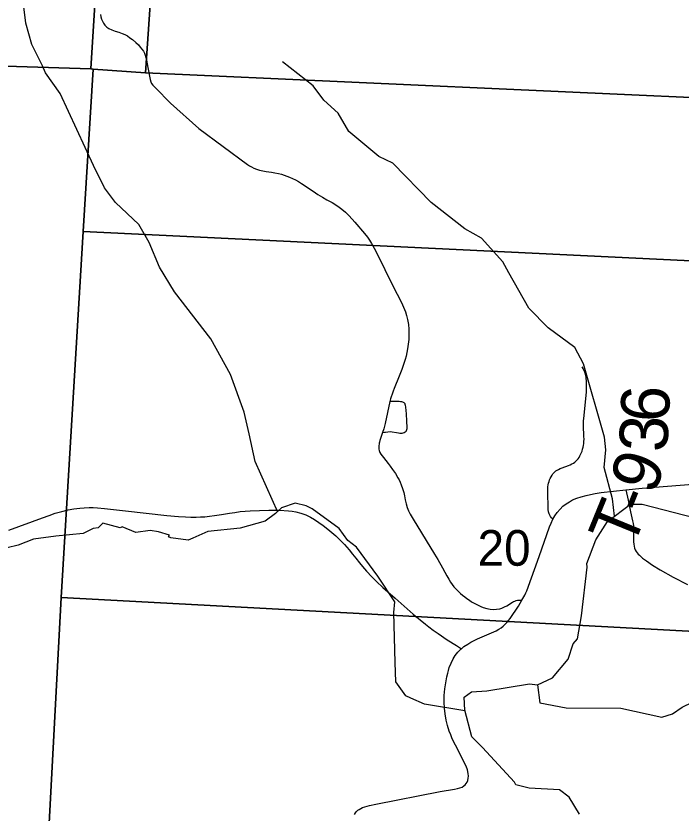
# Model space of a CAD drawing. Extents: x -2.1 to 31.9, y 6.3 to 28.3.
# Drawn here: x 1.171 to 1.952, y 21.042 to 21.978 of the extents above; entities that cross this region are included whole.
import ezdxf

# ---------------------------------------------------------------- set-up
doc = ezdxf.new("R2010")
doc.units = 0
for name, color, linetype in [('GM_X_County_Road', 7, 'Continuous'), ('GM_X_Minor_River', 7, 'Continuous'), ('GM_X_Section', 7, 'Continuous'), ('GM_X_Section_Text', 7, 'Continuous'), ('GM_X_State_Route', 7, 'Continuous'), ('GM_X_Township_Road', 7, 'Continuous'), ('GM_X_Township_Road_Text', 7, 'Continuous')]:
    doc.layers.add(name, color=color, linetype=linetype)

msp = doc.modelspace()

# ---------------------------------------------------------------- linework, layer by layer
at = {"layer": 'GM_X_County_Road'}
for points in [[(1.27034, 21.9797), (1.27105, 21.97669), (1.27184, 21.97421), (1.27282, 21.97174), (1.27399, 21.96952), (1.27563, 21.9671), (1.27778, 21.96488), (1.28039, 21.96305), (1.28387, 21.96149), (1.2877, 21.9601), (1.29221, 21.95868), (1.29579, 21.95744), (1.29912, 21.95607), (1.30215, 21.95434), (1.30508, 21.95238), (1.30795, 21.95009), (1.31196, 21.94681), (1.315, 21.94394), (1.31727, 21.94141), (1.31909, 21.93898), (1.32083, 21.93645), (1.32214, 21.93402), (1.32309, 21.93167), (1.32388, 21.92923), (1.32449, 21.9268), (1.32509, 21.92375), (1.32786, 21.90712), (1.32864, 21.90334), (1.32943, 21.90073), (1.33047, 21.89857), (1.33191, 21.89648), (1.33508, 21.89339), (1.35288, 21.87551), (1.38613, 21.84593), (1.44319, 21.80357), (1.44541, 21.80206), (1.44769, 21.8007), (1.4505, 21.79932), (1.45383, 21.79802), (1.45735, 21.79691), (1.46094, 21.79613), (1.46505, 21.79545), (1.46804, 21.79501), (1.47138, 21.79453), (1.47516, 21.7939), (1.47935, 21.79297), (1.483, 21.79199), (1.4862, 21.79101), (1.48934, 21.78984), (1.49244, 21.78862), (1.49606, 21.78703), (1.49953, 21.78539), (1.5031, 21.78344), (1.50663, 21.78137), (1.52014, 21.77205), (1.52582, 21.76835), (1.53104, 21.76522), (1.53644, 21.76212), (1.54252, 21.75879), (1.54934, 21.75455), (1.55383, 21.75129), (1.55804, 21.74768), (1.56243, 21.74334), (1.56912, 21.73604), (1.58046, 21.72269), (1.58385, 21.71834), (1.58637, 21.71477), (1.58881, 21.71069), (1.59177, 21.70529), (1.59491, 21.69963), (1.6137, 21.66102), (1.62382, 21.64163), (1.6263, 21.63615), (1.62845, 21.6308), (1.62988, 21.6263), (1.631, 21.62153), (1.63204, 21.61572), (1.63249, 21.61037), (1.63269, 21.60375), (1.63253, 21.59821), (1.63195, 21.59269), (1.63111, 21.58735), (1.63026, 21.58298), (1.62927, 21.57867), (1.62817, 21.57462), (1.62706, 21.57104), (1.62427, 21.56286), (1.62124, 21.55517), (1.61534, 21.54057), (1.61409, 21.53744), (1.61286, 21.53391), (1.61188, 21.53104), (1.61109, 21.52836), (1.61028, 21.52528)], [(1.61028, 21.52528), (1.60758, 21.51265), (1.60474, 21.49939), (1.60409, 21.49633), (1.60317, 21.49313), (1.60181, 21.48908), (1.5989, 21.48094), (1.59845, 21.47942), (1.59804, 21.47783), (1.59773, 21.47653), (1.59752, 21.47538), (1.59738, 21.47392), (1.59732, 21.47251), (1.59735, 21.471), (1.59746, 21.46949), (1.59771, 21.468), (1.59807, 21.46674), (1.59864, 21.46542), (1.59975, 21.46367), (1.60272, 21.45978), (1.60832, 21.4526), (1.61061, 21.44966), (1.6135, 21.44562), (1.61697, 21.44077), (1.61981, 21.43597), (1.62117, 21.43344), (1.62245, 21.43058), (1.62369, 21.42743), (1.625, 21.42343), (1.62648, 21.41873), (1.62743, 21.41455), (1.62839, 21.40986), (1.62935, 21.40533), (1.63058, 21.40102), (1.63219, 21.39715), (1.6343, 21.39319), (1.63777, 21.38722), (1.66287, 21.34609), (1.66669, 21.33983), (1.67199, 21.33031), (1.67468, 21.32523), (1.67713, 21.32081), (1.67946, 21.31686), (1.68159, 21.31341), (1.68349, 21.31067), (1.68549, 21.30803), (1.68741, 21.30578), (1.68924, 21.30379), (1.69123, 21.30186), (1.69332, 21.2999), (1.69569, 21.29795), (1.69819, 21.29596), (1.70078, 21.29413), (1.70383, 21.29203), (1.70631, 21.29046), (1.70917, 21.28879), (1.71472, 21.28595), (1.71712, 21.28488), (1.71991, 21.28375), (1.72413, 21.28247), (1.72785, 21.28176), (1.73164, 21.28144), (1.73546, 21.28157), (1.73922, 21.28224), (1.74164, 21.283), (1.74483, 21.28434), (1.74752, 21.28576), (1.75421, 21.28969), (1.75554, 21.29047), (1.75701, 21.29116), (1.75857, 21.29169), (1.76014, 21.29203), (1.762, 21.29218), (1.76539, 21.29221)], [(1.88742, 21.42157), (1.89001, 21.40957), (1.893, 21.39573), (1.89528, 21.38515), (1.89581, 21.38217), (1.8962, 21.3796), (1.8964, 21.37656), (1.89647, 21.37346), (1.89647, 21.36064), (1.89657, 21.35808), (1.89693, 21.35555), (1.89746, 21.35317), (1.89825, 21.35124), (1.8993, 21.3495), (1.90048, 21.34797), (1.90192, 21.34633), (1.9033, 21.34493), (1.90499, 21.34336), (1.90709, 21.34163), (1.91157, 21.33827), (1.91875, 21.3334), (1.92773, 21.32782), (1.9428, 21.31928), (1.95972, 21.31045)], [(1.16269, 21.37436), (1.20229, 21.38882), (1.21038, 21.39177), (1.21737, 21.39414), (1.22506, 21.39641), (1.23236, 21.39828), (1.23915, 21.39947), (1.24615, 21.40026), (1.25147, 21.40065), (1.25729, 21.40085), (1.26192, 21.40085), (1.26715, 21.40055), (1.27522, 21.39986), (1.3, 21.39688), (1.3485, 21.39175), (1.36216, 21.39044), (1.37018, 21.38992), (1.37648, 21.38979), (1.38293, 21.38979), (1.38778, 21.38992), (1.39291, 21.39018), (1.3983, 21.3907), (1.40446, 21.39154), (1.41249, 21.39267), (1.42194, 21.3943), (1.42812, 21.3953), (1.43444, 21.39609), (1.44626, 21.39688), (1.45711, 21.39745), (1.46828, 21.39771), (1.48067, 21.39771), (1.49115, 21.39719), (1.49548, 21.39669), (1.49992, 21.39601), (1.50574, 21.3945), (1.51156, 21.3922), (1.51697, 21.38957), (1.5218, 21.38681), (1.52703, 21.38346), (1.53186, 21.38001), (1.53737, 21.37567), (1.54229, 21.37162), (1.54674, 21.36769), (1.55147, 21.36306), (1.55689, 21.35744), (1.56229, 21.35138), (1.56643, 21.34636), (1.57018, 21.34163), (1.57461, 21.33601), (1.57825, 21.33158), (1.58289, 21.32616), (1.58913, 21.31959), (1.59442, 21.31403), (1.6022, 21.30694), (1.61659, 21.29452), (1.63768, 21.27589), (1.65207, 21.26387), (1.65601, 21.26081), (1.66104, 21.25707), (1.66715, 21.25293), (1.67752, 21.24568), (1.68841, 21.23889), (1.69422, 21.23526)]]:
    msp.add_lwpolyline(points, dxfattribs=at)
at = {"layer": 'GM_X_Minor_River'}
for points in [[(1.47874, 21.39561), (1.45219, 21.45492), (1.44524, 21.48741), (1.43921, 21.51304), (1.42316, 21.55721), (1.39986, 21.59896), (1.35731, 21.65422), (1.33966, 21.68287), (1.3277, 21.71211), (1.31548, 21.733), (1.28792, 21.75893), (1.27521, 21.77604), (1.2624, 21.80227), (1.22302, 21.88704), (1.20598, 21.91113), (1.20245, 21.91921), (1.18998, 21.94429), (1.18281, 21.96957), (1.17979, 21.99473), (1.17551, 22.00322)], [(1.87414, 21.39089), (1.8717, 21.41107), (1.86185, 21.44783), (1.864, 21.46865), (1.86218, 21.48351), (1.83758, 21.56972), (1.82757, 21.58864), (1.79614, 21.61166), (1.77341, 21.63478), (1.75011, 21.67652), (1.74294, 21.68928), (1.7177, 21.71703), (1.69837, 21.72789), (1.65887, 21.75876), (1.61378, 21.80499), (1.59739, 21.8131), (1.56679, 21.83836), (1.562, 21.84231), (1.54941, 21.86359), (1.53287, 21.87893), (1.52016, 21.89603), (1.48435, 21.92412)], [(1.69839, 21.16231), (1.65093, 21.17017), (1.63505, 21.17735), (1.629, 21.17999), (1.61726, 21.19631), (1.61649, 21.21911), (1.61492, 21.27763), (1.61604, 21.29017), (1.59598, 21.32053), (1.571, 21.35429), (1.56079, 21.36224), (1.55057, 21.37627), (1.51917, 21.39937), (1.51199, 21.40278), (1.49913, 21.40616), (1.48288, 21.40042), (1.47608, 21.39394), (1.464, 21.38479), (1.43452, 21.37673), (1.39672, 21.37283), (1.37896, 21.36481), (1.37329, 21.36251), (1.35325, 21.3655), (1.35023, 21.36664), (1.35136, 21.36854), (1.33851, 21.37231), (1.32868, 21.37418), (1.31205, 21.37148), (1.29579, 21.37828), (1.29352, 21.37714), (1.2731, 21.38278), (1.26781, 21.37707), (1.26177, 21.37629), (1.25005, 21.37057), (1.21792, 21.36744), (1.19184, 21.36396), (1.17371, 21.35669), (1.16086, 21.35362)], [(1.83287, 21.04105), (1.82076, 21.06116), (1.80941, 21.06949), (1.77387, 21.07168), (1.75837, 21.07544), (1.75648, 21.07847), (1.71902, 21.11942), (1.70653, 21.13193), (1.69819, 21.16307), (1.69742, 21.17827), (1.70611, 21.18475), (1.72425, 21.18594), (1.77414, 21.19406), (1.78359, 21.19294), (1.80135, 21.20097), (1.81947, 21.22306), (1.8255, 21.24094), (1.83041, 21.24703), (1.8353, 21.27365), (1.84205, 21.33106), (1.84167, 21.33523), (1.85223, 21.36301), (1.86582, 21.38471), (1.89264, 21.40492), (1.90663, 21.40496), (1.96863, 21.38878)], [(1.78359, 21.19294), (1.78641, 21.1718), (1.81714, 21.16579), (1.88162, 21.16556), (1.92943, 21.15503), (1.94231, 21.15886), (1.9533, 21.16648), (1.96542, 21.17259), (1.99994, 21.17), (2.02916, 21.16247), (2.05535, 21.15113), (2.0903, 21.12955), (2.11497, 21.12314), (2.14916, 21.0989), (2.16093, 21.09095), (2.18483, 21.0891), (2.24512, 21.09531), (2.32482, 21.07345), (2.34834, 21.0697), (2.35974, 21.06212), (2.3643, 21.05871)]]:
    msp.add_lwpolyline(points, dxfattribs=at)
at = {"layer": 'GM_X_Section'}
for points in [[(1.31019, 22.73073), (1.25907, 21.91577), (0.77277, 21.931), (0.82184, 22.74075)], [(1.37956, 22.72918), (1.3414, 22.17396), (1.32333, 21.91114), (1.26179, 21.91558), (1.25907, 21.91577), (1.31019, 22.73073)], [(1.3414, 22.17396), (2.12451, 22.13845), (2.30887, 22.13009), (2.29227, 21.86725), (1.32333, 21.91114)], [(0.77277, 21.931), (1.25907, 21.91577), (1.26179, 21.91558), (1.25012, 21.72495), (1.22439, 21.29531), (1.2015, 20.86872), (0.16057, 20.92297), (0.22471, 21.95065)], [(1.32333, 21.91114), (2.29227, 21.86725), (2.28013, 21.67512), (1.25012, 21.72495), (1.26179, 21.91558)], [(1.25012, 21.72495), (2.28013, 21.67512), (2.25264, 21.24002), (1.22439, 21.29531)], [(2.25264, 21.24002), (2.2269, 20.81748), (1.2015, 20.86872), (1.22439, 21.29531)]]:
    msp.add_lwpolyline(points, close=True, dxfattribs=at)
at = {"layer": 'GM_X_State_Route'}
for points in [[(1.70182, 21.24071), (1.70549, 21.24289), (1.70939, 21.2449), (1.7132, 21.24666), (1.73507, 21.25641), (1.73828, 21.25817), (1.74096, 21.25993), (1.74318, 21.26169), (1.74545, 21.26373), (1.74755, 21.2659), (1.75145, 21.27073), (1.76138, 21.28505), (1.76539, 21.29221), (1.7686, 21.2981), (1.76991, 21.30078), (1.77099, 21.30335), (1.78555, 21.34336), (1.7979, 21.37818), (1.79959, 21.38247), (1.80173, 21.38721), (1.80395, 21.39105), (1.80671, 21.3951), (1.81015, 21.39916), (1.81352, 21.40253), (1.81735, 21.40544), (1.82103, 21.40781), (1.82486, 21.40988), (1.82968, 21.41195), (1.83481, 21.41363), (1.84071, 21.41524), (1.84584, 21.41639), (1.85128, 21.41731), (1.85853, 21.41839), (1.88742, 21.42157), (1.90644, 21.42366), (1.98099, 21.42947)], [(1.56857, 21.04069), (1.57001, 21.04282), (1.57127, 21.04436), (1.57254, 21.04558), (1.57403, 21.04673), (1.57603, 21.0479), (1.57833, 21.04893), (1.58091, 21.04985), (1.58349, 21.0506), (1.58644, 21.05127), (1.59373, 21.05274), (1.66923, 21.0677), (1.68613, 21.07038), (1.6896, 21.071), (1.69258, 21.07182), (1.69497, 21.07286), (1.6972, 21.07426), (1.69874, 21.07555), (1.70001, 21.07709), (1.70102, 21.0788), (1.70178, 21.08063), (1.70238, 21.08316), (1.70258, 21.08573), (1.70239, 21.08893), (1.70145, 21.09329), (1.69984, 21.09737), (1.68721, 21.12202), (1.68512, 21.12649), (1.68315, 21.13075), (1.68167, 21.13437), (1.68001, 21.13865), (1.67802, 21.145), (1.67649, 21.15151), (1.67511, 21.1587), (1.67434, 21.16559), (1.6739, 21.17245), (1.67394, 21.17649), (1.67406, 21.18027), (1.67432, 21.18414), (1.67473, 21.18811), (1.67547, 21.19303), (1.67626, 21.19768), (1.67715, 21.20206), (1.67817, 21.20641), (1.67906, 21.2098), (1.68008, 21.21307), (1.68223, 21.21844), (1.68476, 21.22356), (1.68698, 21.22709), (1.69012, 21.23122), (1.69349, 21.23467), (1.69422, 21.23526), (1.69731, 21.23773), (1.70182, 21.24071)]]:
    msp.add_lwpolyline(points, dxfattribs=at)
at = {"layer": 'GM_X_Township_Road'}
for points in [[(1.80173, 21.38721), (1.80015, 21.38882), (1.79906, 21.39026), (1.79809, 21.3918), (1.79722, 21.3937), (1.79662, 21.39599), (1.7963, 21.39858), (1.79613, 21.40145), (1.79573, 21.41782), (1.7957, 21.42059), (1.79574, 21.42293), (1.79586, 21.42515), (1.79612, 21.42745), (1.79665, 21.42968), (1.79716, 21.43158), (1.7979, 21.43347), (1.7986, 21.43499), (1.79954, 21.43683), (1.80078, 21.43894), (1.80177, 21.44041), (1.80281, 21.44161), (1.80402, 21.44282), (1.80528, 21.44383), (1.80674, 21.44482), (1.80838, 21.44576), (1.81037, 21.44672), (1.81239, 21.44754), (1.82009, 21.45044), (1.82211, 21.4512), (1.82406, 21.45214), (1.8257, 21.45309), (1.82738, 21.4543), (1.82876, 21.4554), (1.83022, 21.45676), (1.83138, 21.45815), (1.83248, 21.45972), (1.83343, 21.46144), (1.83426, 21.46312), (1.83507, 21.46493), (1.83588, 21.46715), (1.83657, 21.46952), (1.83722, 21.47193), (1.83764, 21.47391), (1.83795, 21.47611), (1.83812, 21.47835), (1.83822, 21.48126), (1.83819, 21.48412), (1.83761, 21.49724), (1.83769, 21.50012), (1.83782, 21.50288), (1.83798, 21.50528), (1.8383, 21.5089), (1.84096, 21.53654), (1.84117, 21.54034), (1.84125, 21.54384), (1.84122, 21.54719), (1.84109, 21.54995), (1.8409, 21.55212), (1.84064, 21.55401), (1.84038, 21.55556), (1.84004, 21.55707), (1.83962, 21.55848), (1.8391, 21.55994), (1.83841, 21.56149), (1.83715, 21.56397), (1.83591, 21.56615)], [(1.60181, 21.48908), (1.60383, 21.48927), (1.6052, 21.4894), (1.61074, 21.49006), (1.62046, 21.48846), (1.62194, 21.48832), (1.62356, 21.48827), (1.62477, 21.48835), (1.62601, 21.48854), (1.62719, 21.48894), (1.62833, 21.48964), (1.62928, 21.4906), (1.6298, 21.4914), (1.6302, 21.49244), (1.63039, 21.49375), (1.63001, 21.50355), (1.62936, 21.51595), (1.62921, 21.51774), (1.62904, 21.51926), (1.62879, 21.52051), (1.62842, 21.52172), (1.6281, 21.52251), (1.62765, 21.52319), (1.62696, 21.52383), (1.62627, 21.52427), (1.62532, 21.52463), (1.62415, 21.52493), (1.6228, 21.52514), (1.62134, 21.52532), (1.61918, 21.52548), (1.61699, 21.5255), (1.61028, 21.52528)]]:
    msp.add_lwpolyline(points, dxfattribs=at)

# ---------------------------------------------------------------- texts
at = {"layer": 'GM_X_Section_Text'}
msp.add_text('20', height=0.041856, rotation=0.00001, dxfattribs=at).set_placement((1.71326, 21.33262))
at = {"layer": 'GM_X_Township_Road_Text'}
for s, rotation, p in [('6', 87.33666, (1.93756, 21.50037)), ('3', 87.29998, (1.93591, 21.46536)), ('9', 70.44443, (1.92069, 21.41457)), ('T', 67.77441, (1.89488, 21.35088)), ('-', 68.08762, (1.91108, 21.39054))]:
    msp.add_text(s, height=0.05682, rotation=rotation, dxfattribs=at).set_placement(p)

doc.saveas('drawing.dxf')
